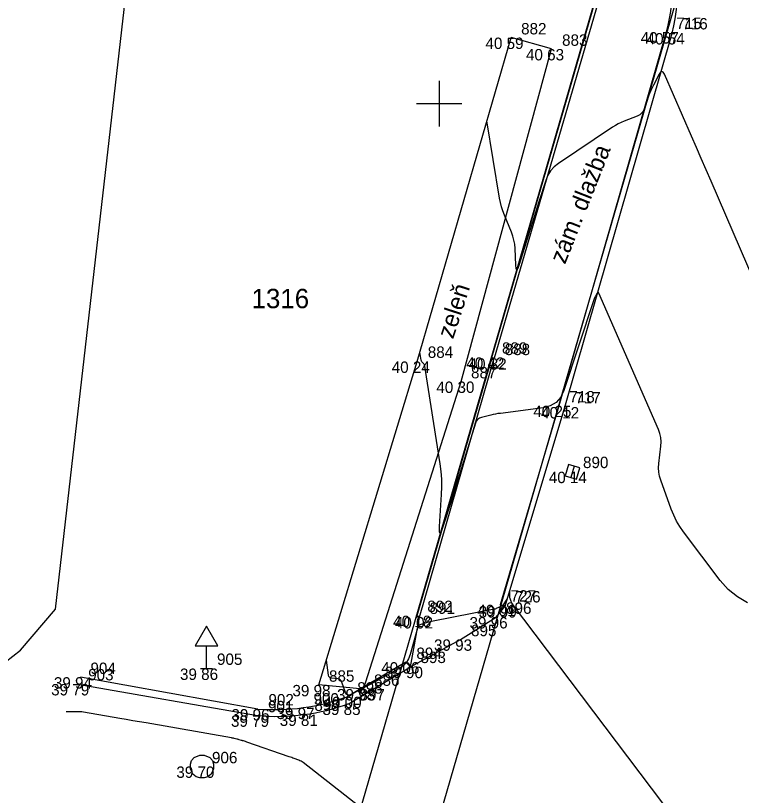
# Model space of a CAD drawing. Extents: x -702257 to -701487, y -1009871 to -1008841.
# Drawn here: x -701709.3 to -701693.36, y -1009140.19 to -1009123.07 of the extents above; entities that cross this region are included whole.
import ezdxf

# ---------------------------------------------------------------- set-up
doc = ezdxf.new("R2010")
doc.units = 0
for name, color, linetype in [('Ex_Major Contours', 7, 'Continuous'), ('Ex_Minor Contours', 7, 'Continuous'), ('Z_body', 7, 'Continuous'), ('Z_body_cisla', 7, 'Continuous'), ('Z_body_vysky_redukovane', 7, 'Continuous'), ('Z_dopravni_znacky', 7, 'Continuous'), ('Z_hektometricka_sit', 7, 'Continuous'), ('Z_katastr_cisla_pozemkova', 7, 'Continuous'), ('Z_katastr_hranice', 7, 'Continuous'), ('Z_komunikace', 7, 'Continuous'), ('Z_obruba', 7, 'Continuous'), ('Z_popisy', 7, 'Continuous'), ('Z_rozhranni', 7, 'Continuous'), ('Z_site_kanalizace_znaky', 7, 'Continuous'), ('Z_zelen_obvod', 7, 'Continuous')]:
    doc.layers.add(name, color=color, linetype=linetype)

# ---------------------------------------------------------------- blocks, each defined once
blk = doc.blocks.new('POINT_DISPLAY')
blk.add_line((0, 0), (0, 0))
blk = doc.blocks.new('Z620')
for p, q in [((-0.23, 0.13), (-0.17, 0.2)), ((-0.17, 0.2), (-0.05, 0.25)), ((-0.05, 0.25), (0.05, 0.25)), ((0.05, 0.25), (0.17, 0.2)), ((0.17, 0.2), (0.23, 0.13)), ((-0.25, 0.05), (-0.23, 0.13)), ((-0.25, -0.05), (-0.25, 0.05)), ((0.23, 0.13), (0.25, 0.05)), ((0.25, 0.05), (0.25, -0.05)), ((-0.2, -0.17), (-0.25, -0.05)), ((-0.13, -0.23), (-0.2, -0.17)), ((0.2, -0.17), (0.13, -0.23)), ((0.25, -0.05), (0.2, -0.17)), ((-0.05, -0.25), (-0.13, -0.23)), ((0.05, -0.25), (-0.05, -0.25)), ((0.13, -0.23), (0.05, -0.25))]:
    blk.add_line(p, q)
blk = doc.blocks.new('Z46260')
for p, q in [((0.13, 0.13), (-0.13, 0.13)), ((-0.13, 0.13), (-0.13, -0.13)), ((0.13, 0), (-0.13, 0)), ((0.13, -0.13), (0.13, 0.13)), ((-0.13, -0.13), (0.13, -0.13))]:
    blk.add_line(p, q)
blk = doc.blocks.new('Z527')
for p, q in [((0, 0.93), (-0.25, 0.5)), ((0.25, 0.5), (0, 0.93)), ((-0.25, 0.5), (0.25, 0.5)), ((0, 0), (0, 0.5)), ((-0.13, 0), (0.13, 0))]:
    blk.add_line(p, q)

msp = doc.modelspace()

# ---------------------------------------------------------------- linework, layer by layer
at = {"layer": 'Ex_Major Contours'}
msp.add_lwpolyline([(-701695.087, -1009140.358), (-701698.386, -1009135.985), (-701698.395, -1009135.972), (-701698.404, -1009135.957), (-701698.411, -1009135.943), (-701698.417, -1009135.927), (-701698.44, -1009135.865), (-701698.445, -1009135.849), (-701698.448, -1009135.833), (-701698.45, -1009135.817), (-701698.451, -1009135.8), (-701698.45, -1009135.729), (-701698.45, -1009135.716), (-701698.452, -1009135.711), (-701698.455, -1009135.715), (-701698.46, -1009135.727), (-701698.491, -1009135.819), (-701698.498, -1009135.84), (-701698.507, -1009135.86), (-701698.517, -1009135.879), (-701698.529, -1009135.898), (-701698.594, -1009135.998), (-701698.6, -1009136.006), (-701698.607, -1009136.013), (-701698.615, -1009136.019), (-701698.623, -1009136.025), (-701698.66, -1009136.044), (-701698.669, -1009136.049), (-701698.678, -1009136.054), (-701698.687, -1009136.058), (-701698.697, -1009136.063), (-701698.746, -1009136.085), (-701698.758, -1009136.09), (-701698.769, -1009136.094), (-701698.781, -1009136.097), (-701698.793, -1009136.1), (-701700.17, -1009136.367), (-701700.2, -1009136.373), (-701700.23, -1009136.381), (-701700.259, -1009136.388), (-701700.288, -1009136.397), (-701700.405, -1009136.433), (-701700.432, -1009136.445), (-701700.453, -1009136.462), (-701700.469, -1009136.484), (-701700.479, -1009136.511), (-701700.638, -1009137.095), (-701700.673, -1009137.19), (-701700.725, -1009137.272), (-701700.792, -1009137.342), (-701700.876, -1009137.399), (-701701.28, -1009137.621), (-701701.354, -1009137.662), (-701701.428, -1009137.702), (-701701.502, -1009137.742), (-701701.576, -1009137.782), (-701701.93, -1009137.972), (-701701.971, -1009137.987), (-701702.006, -1009137.984), (-701702.034, -1009137.963), (-701702.056, -1009137.924), (-701702.14, -1009137.697), (-701702.154, -1009137.669), (-701702.173, -1009137.649), (-701702.198, -1009137.635), (-701702.228, -1009137.628), (-701702.359, -1009137.615), (-701702.389, -1009137.608), (-701702.411, -1009137.593), (-701702.425, -1009137.572), (-701702.433, -1009137.543), (-701702.474, -1009137.214)], dxfattribs=at)
at = {"layer": 'Ex_Minor Contours'}
for points in [[(-701692.434, -1009130.385), (-701694.026, -1009126.702), (-701694.133, -1009126.455), (-701694.241, -1009126.207), (-701694.348, -1009125.96), (-701694.456, -1009125.713), (-701695.051, -1009124.356), (-701695.078, -1009124.309), (-701695.107, -1009124.293), (-701695.137, -1009124.307), (-701695.168, -1009124.351), (-701695.294, -1009124.591), (-701695.324, -1009124.651), (-701695.352, -1009124.712), (-701695.377, -1009124.775), (-701695.399, -1009124.839), (-701695.484, -1009125.095), (-701695.51, -1009125.155), (-701695.547, -1009125.204), (-701695.594, -1009125.243), (-701695.652, -1009125.273), (-701695.933, -1009125.382), (-701696, -1009125.41), (-701696.065, -1009125.442), (-701696.128, -1009125.477), (-701696.189, -1009125.516), (-701697.379, -1009126.313), (-701697.473, -1009126.388), (-701697.551, -1009126.474), (-701697.612, -1009126.573), (-701697.658, -1009126.684), (-701697.807, -1009127.153), (-701697.844, -1009127.27), (-701697.882, -1009127.387), (-701697.919, -1009127.504), (-701697.956, -1009127.621), (-701698.25, -1009128.555), (-701698.275, -1009128.621), (-701698.294, -1009128.642), (-701698.307, -1009128.617), (-701698.315, -1009128.547), (-701698.332, -1009128.176), (-701698.34, -1009128.085), (-701698.357, -1009127.994), (-701698.38, -1009127.906), (-701698.412, -1009127.82), (-701698.567, -1009127.448), (-701698.602, -1009127.356), (-701698.631, -1009127.263), (-701698.655, -1009127.169), (-701698.674, -1009127.073), (-701698.95, -1009125.378)], [(-701693.226, -1009135.956), (-701693.45, -1009135.829), (-701693.65, -1009135.666), (-701693.825, -1009135.468), (-701694.629, -1009134.402), (-701694.711, -1009134.284), (-701694.783, -1009134.162), (-701694.847, -1009134.034), (-701694.901, -1009133.901), (-701695.13, -1009133.268), (-701695.158, -1009133.178), (-701695.174, -1009133.086), (-701695.179, -1009132.993), (-701695.173, -1009132.898), (-701695.127, -1009132.519), (-701695.122, -1009132.424), (-701695.129, -1009132.332), (-701695.149, -1009132.242), (-701695.181, -1009132.153), (-701696.491, -1009129.161), (-701696.5, -1009129.145), (-701696.51, -1009129.14), (-701696.52, -1009129.144), (-701696.531, -1009129.16), (-701696.574, -1009129.242), (-701696.585, -1009129.262), (-701696.594, -1009129.283), (-701696.603, -1009129.305), (-701696.61, -1009129.326), (-701697.26, -1009131.297), (-701697.33, -1009131.446), (-701697.429, -1009131.558), (-701697.559, -1009131.635), (-701697.718, -1009131.675), (-701698.655, -1009131.798), (-701698.708, -1009131.805), (-701698.76, -1009131.815), (-701698.812, -1009131.825), (-701698.864, -1009131.838), (-701699.07, -1009131.889), (-701699.117, -1009131.907), (-701699.155, -1009131.934), (-701699.184, -1009131.971), (-701699.204, -1009132.017), (-701699.549, -1009133.122), (-701699.594, -1009133.268), (-701699.64, -1009133.415), (-701699.686, -1009133.561), (-701699.732, -1009133.708), (-701699.917, -1009134.293), (-701699.956, -1009134.402), (-701699.981, -1009134.436), (-701699.992, -1009134.396), (-701699.989, -1009134.28), (-701699.945, -1009133.578), (-701699.939, -1009133.41), (-701699.943, -1009133.243), (-701699.955, -1009133.076), (-701699.977, -1009132.909), (-701700.316, -1009130.759), (-701700.319, -1009130.747), (-701700.323, -1009130.735), (-701700.329, -1009130.724), (-701700.337, -1009130.714), (-701700.372, -1009130.675), (-701700.379, -1009130.664), (-701700.386, -1009130.653), (-701700.39, -1009130.642), (-701700.393, -1009130.629), (-701700.421, -1009130.457)], [(-701701.697, -1009140.476), (-701702.986, -1009139.466), (-701703.009, -1009139.45), (-701703.032, -1009139.436), (-701703.057, -1009139.423), (-701703.082, -1009139.413), (-701703.187, -1009139.374), (-701703.213, -1009139.364), (-701703.239, -1009139.354), (-701703.265, -1009139.345), (-701703.292, -1009139.336), (-701704.225, -1009139.015), (-701704.254, -1009139.005), (-701704.301, -1009138.99), (-701704.311, -1009138.987), (-701704.32, -1009138.984), (-701704.33, -1009138.981), (-701704.34, -1009138.978), (-701704.393, -1009138.963), (-701704.405, -1009138.959), (-701704.417, -1009138.956), (-701704.429, -1009138.953), (-701704.441, -1009138.95), (-701704.503, -1009138.935), (-701704.518, -1009138.931), (-701704.532, -1009138.928), (-701704.547, -1009138.925), (-701704.561, -1009138.923), (-701706.437, -1009138.595), (-701706.582, -1009138.57), (-701706.727, -1009138.545), (-701706.872, -1009138.52), (-701707.016, -1009138.495), (-701707.811, -1009138.359), (-701707.849, -1009138.354), (-701707.886, -1009138.35), (-701707.924, -1009138.348), (-701707.962, -1009138.348), (-701708.19, -1009138.351)]]:
    msp.add_lwpolyline(points, dxfattribs=at)
at = {"layer": 'Z_hektometricka_sit'}
for p, q in [((-701700, -1009124.5), (-701700, -1009125.5)), ((-701700, -1009124.5), (-701700, -1009125.5)), ((-701700.5, -1009125), (-701699.5, -1009125)), ((-701700.5, -1009125), (-701699.5, -1009125))]:
    msp.add_line(p, q, dxfattribs=at)
at = {"layer": 'Z_katastr_hranice'}
for p, q in [((-701708.43, -1009136.1), (-701705.82, -1009113.32)), ((-701703.95, -1009148.13), (-701696.38, -1009122.06)), ((-701708.88, -1009171.29), (-701694.63, -1009122.18)), ((-701709.2, -1009137), (-701708.43, -1009136.1)), ((-701709.85, -1009137.5), (-701709.2, -1009137))]:
    msp.add_line(p, q, dxfattribs=at)
at = {"layer": 'Z_komunikace'}
for p, q in [((-701697.24, -1009131.66), (-701694.88, -1009123.45)), ((-701698.55, -1009136.03), (-701697.24, -1009131.66)), ((-701698.75, -1009136.27), (-701698.55, -1009136.03)), ((-701699.53, -1009136.76), (-701698.75, -1009136.27)), ((-701700.63, -1009137.36), (-701699.53, -1009136.76)), ((-701701.98, -1009138.17), (-701700.63, -1009137.36)), ((-701707.94, -1009137.74), (-701703.99, -1009138.43))]:
    msp.add_line(p, q, dxfattribs=at)
for centre, major_axis, ratio, start_param, end_param in [((-701698.479, -1009122.504), (0.259, 3.78), 0.981485, 4.527221, 5.193564), ((-701703.572, -1009133.857), (4.536, -0.84), 0.995375, 4.803915, 5.247074)]:
    msp.add_ellipse(centre, major_axis=major_axis, ratio=ratio, start_param=start_param, end_param=end_param, dxfattribs=at)
at = {"layer": 'Z_obruba'}
for p, q in [((-701698.84, -1009130.57), (-701696.57, -1009122.76)), ((-701696.51, -1009122.77), (-701698.79, -1009130.59)), ((-701695.01, -1009123.43), (-701697.37, -1009131.63)), ((-701698.84, -1009130.57), (-701700.49, -1009136.24)), ((-701700.43, -1009136.27), (-701698.79, -1009130.59)), ((-701697.37, -1009131.63), (-701698.66, -1009136)), ((-701698.55, -1009136.03), (-701698.66, -1009136)), ((-701700.49, -1009136.24), (-701700.43, -1009136.27)), ((-701700.73, -1009137.26), (-701702.02, -1009138.02)), ((-701700.63, -1009137.36), (-701700.73, -1009137.26)), ((-701703.98, -1009138.29), (-701707.88, -1009137.59))]:
    msp.add_line(p, q, dxfattribs=at)
for centre, major_axis, ratio, start_param, end_param in [((-701698.37, -1009122.491), (1.217, 3.285), 0.995967, 4.794436, 5.493322), ((-701703.63, -1009133.647), (4.664, -0.35), 0.995405, 4.711947, 5.138235)]:
    msp.add_ellipse(centre, major_axis=major_axis, ratio=ratio, start_param=start_param, end_param=end_param, dxfattribs=at)
at = {"layer": 'Z_rozhranni'}
msp.add_line((-701700.63, -1009137.36), (-701700.43, -1009136.27), dxfattribs=at)
at = {"layer": 'Z_zelen_obvod'}
for p, q in [((-701700.48, -1009130.66), (-701698.42, -1009123.55)), ((-701697.53, -1009123.8), (-701698.42, -1009123.55)), ((-701699.52, -1009131.1), (-701697.53, -1009123.8)), ((-701702.64, -1009137.76), (-701700.48, -1009130.66)), ((-701701.66, -1009137.85), (-701699.52, -1009131.1)), ((-701701.66, -1009137.85), (-701702.64, -1009137.76))]:
    msp.add_line(p, q, dxfattribs=at)

# ---------------------------------------------------------------- block references
at = {"layer": 'Z_body'}
for p in [(-701695.01, -1009123.43), (-701694.88, -1009123.45), (-701698.42, -1009123.55), (-701697.53, -1009123.8), (-701700.48, -1009130.66), (-701698.84, -1009130.57), (-701698.79, -1009130.59), (-701699.52, -1009131.1), (-701697.37, -1009131.63), (-701697.24, -1009131.66), (-701697.07, -1009133.08), (-701698.66, -1009136), (-701698.55, -1009136.03), (-701700.49, -1009136.24), (-701700.43, -1009136.27), (-701698.75, -1009136.27), (-701699.53, -1009136.76), (-701700.73, -1009137.26), (-701700.63, -1009137.36), (-701705.11, -1009137.4), (-701707.88, -1009137.59), (-701707.94, -1009137.74), (-701702.64, -1009137.76), (-701701.66, -1009137.85), (-701702.02, -1009138.02), (-701701.98, -1009138.17), (-701703.98, -1009138.29), (-701702.99, -1009138.26), (-701703.99, -1009138.43), (-701702.96, -1009138.41), (-701705.21, -1009139.55)]:
    msp.add_blockref('POINT_DISPLAY', p, dxfattribs=at)
at = {"layer": 'Z_dopravni_znacky'}
msp.add_blockref('Z527', (-701705.11, -1009137.4), dxfattribs=at)
at = {"layer": 'Z_site_kanalizace_znaky', "rotation": 73.8}
msp.add_blockref('Z46260', (-701697.07, -1009133.08), dxfattribs=at)
at = {"layer": 'Z_site_kanalizace_znaky'}
msp.add_blockref('Z620', (-701705.21, -1009139.55), dxfattribs=at)

# ---------------------------------------------------------------- texts
at = {"layer": 'Z_body_cisla'}
for s, p in [('715', (-701694.79, -1009123.36)), ('716', (-701694.66, -1009123.37)), ('882', (-701698.2, -1009123.48)), ('883', (-701697.3, -1009123.73)), ('884', (-701700.25, -1009130.58)), ('889', (-701698.62, -1009130.49)), ('888', (-701698.56, -1009130.52)), ('887', (-701699.3, -1009131.03)), ('718', (-701697.14, -1009131.56)), ('717', (-701697.01, -1009131.58)), ('890', (-701696.84, -1009133)), ('727', (-701698.43, -1009135.93)), ('726', (-701698.33, -1009135.95)), ('892', (-701700.26, -1009136.16)), ('891', (-701700.21, -1009136.2)), ('896', (-701698.53, -1009136.2)), ('895', (-701699.3, -1009136.69)), ('894', (-701700.5, -1009137.19)), ('893', (-701700.41, -1009137.28)), ('905', (-701704.88, -1009137.32)), ('904', (-701707.66, -1009137.52)), ('903', (-701707.71, -1009137.66)), ('885', (-701702.42, -1009137.69)), ('886', (-701701.43, -1009137.78)), ('898', (-701701.8, -1009137.95)), ('897', (-701701.75, -1009138.1)), ('902', (-701703.75, -1009138.21)), ('900', (-701702.76, -1009138.19)), ('901', (-701703.76, -1009138.36)), ('899', (-701702.74, -1009138.33)), ('906', (-701704.99, -1009139.48))]:
    msp.add_text(s, height=0.25, dxfattribs=at).set_placement(p)
at = {"layer": 'Z_body_vysky_redukovane'}
for s, p in [('40 57', (-701695.573, -1009123.68)), ('40 54', (-701695.443, -1009123.7)), ('40 59', (-701698.983, -1009123.8)), ('40 63', (-701698.093, -1009124.05)), ('40 24', (-701701.042, -1009130.91)), ('40 42', (-701699.403, -1009130.82)), ('40 32', (-701699.353, -1009130.84)), ('40 30', (-701700.062, -1009131.35)), ('40 25', (-701697.932, -1009131.88)), ('40 12', (-701697.761, -1009131.91)), ('40 14', (-701697.591, -1009133.33)), ('40 01', (-701699.16, -1009136.25)), ('39 99', (-701699.133, -1009136.28)), ('40 18', (-701701.011, -1009136.49)), ('40 02', (-701700.972, -1009136.52)), ('39 96', (-701699.333, -1009136.52)), ('39 93', (-701700.113, -1009137.01)), ('40 06', (-701701.272, -1009137.51)), ('39 90', (-701701.193, -1009137.61)), ('39 86', (-701705.693, -1009137.65)), ('39 94', (-701708.463, -1009137.84)), ('39 79', (-701708.523, -1009137.99)), ('39 98', (-701703.223, -1009138.01)), ('39 98', (-701702.243, -1009138.1)), ('40 00', (-701702.541, -1009138.27)), ('39 85', (-701702.563, -1009138.42)), ('39 96', (-701704.563, -1009138.54)), ('39 97', (-701703.573, -1009138.51)), ('39 79', (-701704.573, -1009138.68)), ('39 81', (-701703.502, -1009138.66)), ('39 70', (-701705.773, -1009139.8))]:
    msp.add_text(s, height=0.25, dxfattribs=at).set_placement(p)
at = {"layer": 'Z_katastr_cisla_pozemkova'}
msp.add_text('1316', height=0.425, dxfattribs=at).set_placement((-701704.121, -1009129.49))
at = {"layer": 'Z_popisy'}
for s, rotation, p in [('zám. dlažba', 68.4, (-701697.235, -1009128.541)), ('zeleň', 72, (-701699.694, -1009130.182))]:
    msp.add_text(s, height=0.38, rotation=rotation, dxfattribs=at).set_placement(p)

doc.saveas('drawing.dxf')
